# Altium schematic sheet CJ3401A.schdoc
size 127 x 101 mm
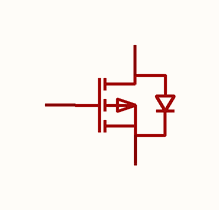
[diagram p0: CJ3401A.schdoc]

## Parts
Q?  cj3401a  [SOT-23_L2.9-W1.3-P1.90-LS2.4-BR]  (value not drawn)

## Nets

Not connected (* = marked no-connect by the designer): Q? 1(G) 2(S) 3(D)

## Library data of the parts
Q? = cj3401a: 数量:1个P沟道;漏源电压(Vdss):30V;连续漏极电流(Id):4.2A;导通电阻(RDS(on)):85mΩ@2.5V;耗散功率(Pd):400mW;阈值电压(Vgs(th)):1.3V;; Manufacturer: CJ(江苏长电/长晶); AddInBom: yes; ModelId: c62791f0466c4ae2a892c056b845b0ca; ModelName: SOT-23-3P_L2.9-W1.3-H1.0-LS2.4-P0.95; ModelTransform: 98.64468,114.173,0,180,0,0,0.001,-0.002,0; Number: 1个P沟道; Drain to Source Voltage: 30V; Current - Continuous Drain(Id): 4.2A; Pd - Power Dissipation: 400mW; Gate Threshold Voltage (Vgs(th)): 1.3V; Input Capacitance(Ciss): 1.05nF; Reverse Transfer Capacitance (Crss@Vds): 85pF; Type: P沟道; Output Capacitance(Coss): 127pF; Vgs: ±12V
